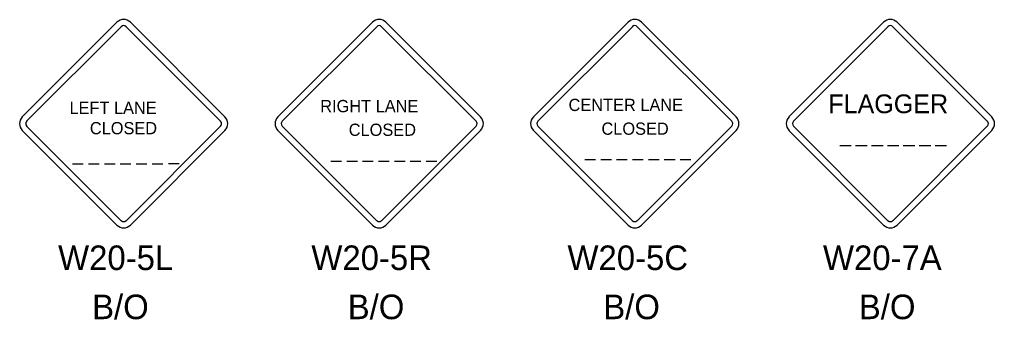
# Model space of a CAD drawing. Extents: x 10000 to 10794, y 10000 to 10499.
# Drawn here: x 10143.6 to 10282.4, y 10206.6 to 10249.3 of the extents above; entities that cross this region are included whole.
import ezdxf

# ---------------------------------------------------------------- set-up
doc = ezdxf.new("R2010")
doc.units = 0
for name, color, linetype in [('DSText', 7, 'Continuous'), ('DSTitle', 7, 'Continuous'), ('PlotBorder_dp', 7, 'Continuous')]:
    doc.layers.add(name, color=color, linetype=linetype)

msp = doc.modelspace()

# ---------------------------------------------------------------- linework, layer by layer
at = {"layer": 'DSText'}
for p, q in [((10143.96, 10235.42), (10157.43, 10248.89)), ((10159.35, 10248.89), (10172.82, 10235.42)), ((10180.35, 10235.42), (10193.82, 10248.89)), ((10195.74, 10248.89), (10209.21, 10235.42)), ((10216.74, 10235.41), (10230.22, 10248.89)), ((10232.13, 10248.89), (10245.61, 10235.41)), ((10253.13, 10235.41), (10266.61, 10248.89)), ((10268.53, 10248.89), (10282, 10235.41)), ((10157.43, 10220.02), (10143.96, 10233.5)), ((10172.82, 10233.5), (10159.35, 10220.02)), ((10193.82, 10220.02), (10180.35, 10233.5)), ((10193.82, 10220.02), (10180.35, 10233.5)), ((10209.21, 10233.5), (10195.74, 10220.02)), ((10209.21, 10233.5), (10195.74, 10220.02)), ((10230.22, 10220.02), (10216.74, 10233.5)), ((10245.61, 10233.5), (10232.13, 10220.02)), ((10266.61, 10220.02), (10253.13, 10233.5)), ((10282, 10233.5), (10268.53, 10220.02)), ((10260.35, 10231.33), (10262, 10231.33)), ((10262.62, 10231.33), (10264.26, 10231.33)), ((10264.88, 10231.33), (10266.53, 10231.33)), ((10267.15, 10231.33), (10268.79, 10231.33)), ((10269.41, 10231.33), (10271.06, 10231.33)), ((10271.68, 10231.33), (10273.32, 10231.33)), ((10273.94, 10231.33), (10275.58, 10231.33)), ((10224.06, 10229.37), (10225.58, 10229.37)), ((10226.32, 10229.37), (10227.85, 10229.37)), ((10228.58, 10229.37), (10230.11, 10229.37)), ((10230.85, 10229.37), (10232.38, 10229.37)), ((10233.11, 10229.37), (10234.64, 10229.37)), ((10235.38, 10229.37), (10236.91, 10229.37)), ((10237.64, 10229.37), (10239.17, 10229.37)), ((10151.11, 10228.74), (10152.64, 10228.74)), ((10153.38, 10228.74), (10154.9, 10228.74)), ((10155.64, 10228.74), (10157.17, 10228.74)), ((10157.91, 10228.74), (10159.43, 10228.74)), ((10160.17, 10228.74), (10161.7, 10228.74)), ((10162.44, 10228.74), (10163.96, 10228.74)), ((10164.79, 10228.79), (10166.31, 10228.79)), ((10187.88, 10229.11), (10189.41, 10229.11)), ((10190.15, 10229.11), (10191.67, 10229.11)), ((10192.41, 10229.11), (10193.94, 10229.11)), ((10194.68, 10229.11), (10196.2, 10229.11)), ((10196.94, 10229.11), (10198.47, 10229.11)), ((10199.21, 10229.11), (10200.73, 10229.11)), ((10201.47, 10229.11), (10203, 10229.11))]:
    msp.add_line(p, q, dxfattribs=at)
for centre, start, end in [((10158.39, 10247.93), 45, 135), ((10194.78, 10247.93), 45, 135), ((10231.17, 10247.93), 45, 135), ((10267.57, 10247.93), 45, 135), ((10144.92, 10234.46), 135, 225), ((10171.86, 10234.46), 315, 45), ((10181.31, 10234.46), 135, 225), ((10208.25, 10234.46), 315, 45), ((10217.7, 10234.46), 135, 225), ((10244.64, 10234.46), 315, 45), ((10254.1, 10234.46), 135, 225), ((10281.04, 10234.46), 315, 45), ((10158.39, 10220.99), 225, 315), ((10194.78, 10220.99), 225, 315), ((10194.78, 10220.99), 225, 315), ((10231.18, 10220.99), 225, 315), ((10267.57, 10220.99), 225, 315)]:
    msp.add_arc(centre, 1.36, start, end, dxfattribs=at)
at = {"layer": 'DSTitle'}
for p, q in [((10144.58, 10234.81), (10158.04, 10248.26)), ((10158.74, 10248.26), (10172.2, 10234.81)), ((10180.97, 10234.8), (10194.43, 10248.26)), ((10195.13, 10248.26), (10208.59, 10234.8)), ((10217.37, 10234.8), (10230.83, 10248.26)), ((10231.52, 10248.26), (10244.98, 10234.8)), ((10253.76, 10234.81), (10267.22, 10248.26)), ((10267.92, 10248.26), (10281.37, 10234.81)), ((10158.04, 10220.65), (10144.58, 10234.11)), ((10172.2, 10234.11), (10158.74, 10220.65)), ((10194.43, 10220.65), (10180.97, 10234.11)), ((10194.43, 10220.65), (10180.97, 10234.11)), ((10208.59, 10234.11), (10195.13, 10220.65)), ((10208.59, 10234.11), (10195.13, 10220.65)), ((10230.83, 10220.65), (10217.37, 10234.11)), ((10244.98, 10234.11), (10231.52, 10220.65)), ((10267.22, 10220.65), (10253.76, 10234.11)), ((10281.37, 10234.11), (10267.92, 10220.65))]:
    msp.add_line(p, q, dxfattribs=at)
for centre, start, end in [((10158.39, 10247.92), 45, 135), ((10194.78, 10247.92), 45, 135), ((10231.17, 10247.92), 45, 135), ((10267.57, 10247.92), 45, 135), ((10144.93, 10234.46), 135, 225), ((10171.85, 10234.46), 315, 45), ((10181.32, 10234.46), 135, 225), ((10208.24, 10234.46), 315, 45), ((10217.71, 10234.46), 135, 225), ((10244.63, 10234.46), 315, 45), ((10254.11, 10234.46), 135, 225), ((10281.03, 10234.46), 315, 45), ((10158.39, 10221), 225, 315), ((10194.78, 10221), 225, 315), ((10194.78, 10221), 225, 315), ((10231.17, 10221), 225, 315), ((10267.57, 10221), 225, 315)]:
    msp.add_arc(centre, 0.49, start, end, dxfattribs=at)

# ---------------------------------------------------------------- texts
at = {"layer": 'PlotBorder_dp'}
for s, height, p in [('RIGHT LANE', 1.742, (10186.38, 10236.09)), ('CENTER LANE', 1.7415, (10221.74, 10236.26)), ('FLAGGER', 2.67, (10258.73, 10235.95)), ('LEFT LANE', 1.74, (10150.68, 10235.84)), ('CLOSED', 1.74, (10153.58, 10232.95)), ('CLOSED', 1.742, (10190.44, 10232.72)), ('CLOSED', 1.74, (10226.43, 10232.88)), ('W20-5L', 3.5, (10149.06, 10213.62)), ('W20-5R', 3.5, (10185.12, 10213.62)), ('W20-5C', 3.5, (10221.59, 10213.62)), ('W20-7A', 3.5, (10257.97, 10213.62)), ('B/O', 3.5, (10153.9, 10206.63)), ('B/O', 3.5, (10190.3, 10206.63)), ('B/O', 3.5, (10226.69, 10206.63)), ('B/O', 3.5, (10263.08, 10206.63))]:
    msp.add_text(s, height=height, dxfattribs=at).set_placement(p)

doc.saveas('drawing.dxf')
